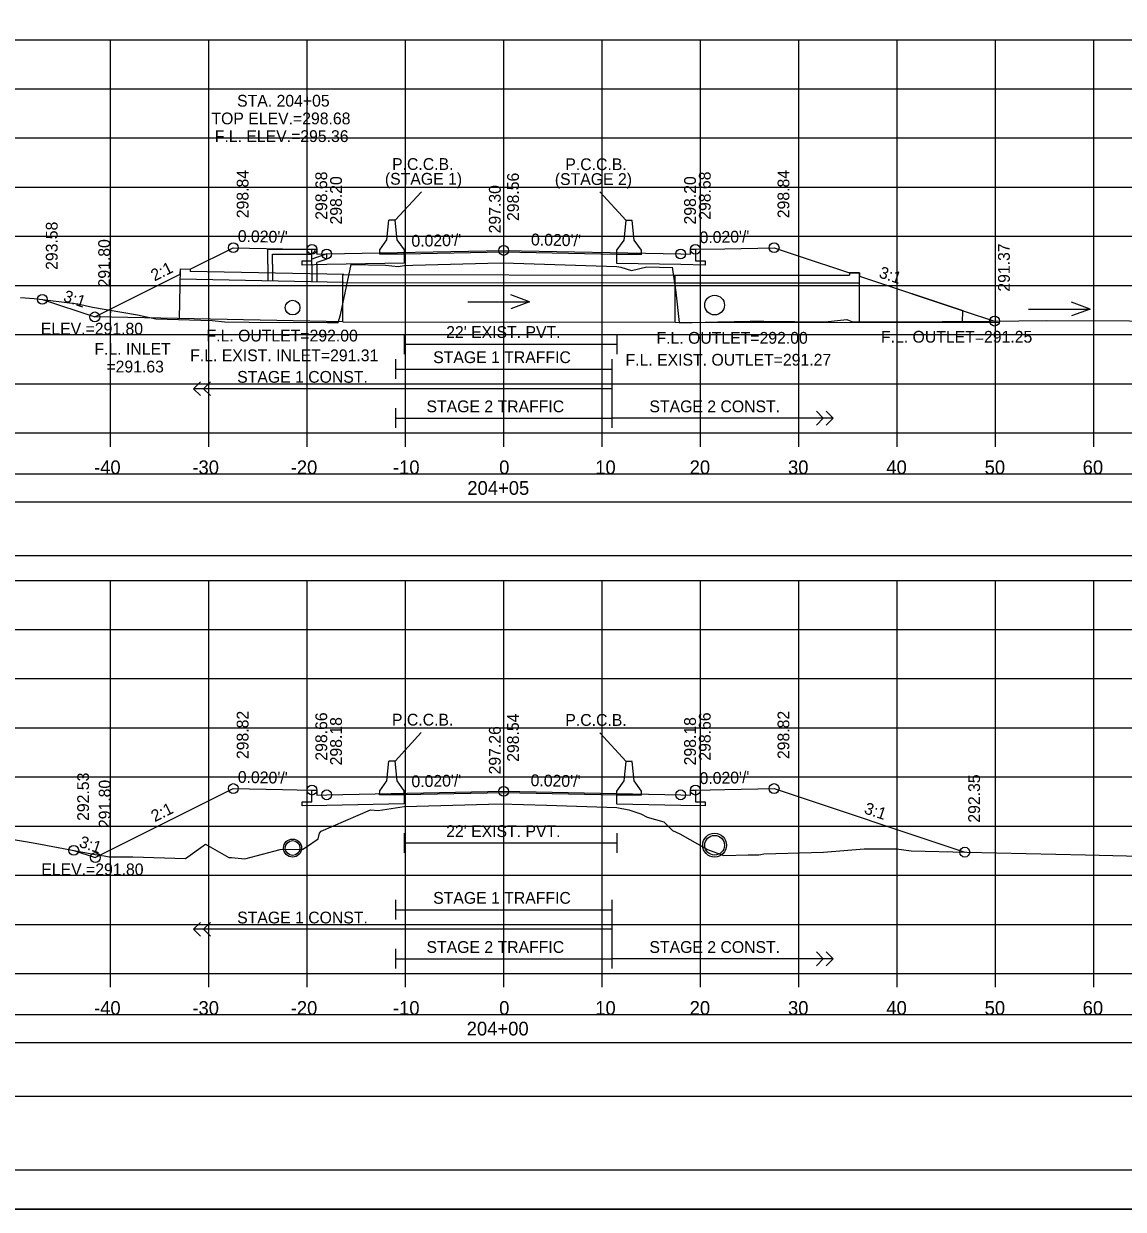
# Model space of a CAD drawing. Extents: x 1368122 to 1710785, y 373130 to 557566.
# Drawn here: x 1369973.4 to 1370085.2, y 373770.3 to 373890.9 of the extents above; entities that cross this region are included whole.
import ezdxf

# ---------------------------------------------------------------- set-up
doc = ezdxf.new("R2010")
doc.units = 0
for name, color, linetype in [('R_Alt Surface', 7, 'Continuous'), ('R_Axis', 7, 'Continuous'), ('R_Axis Annot', 7, 'Continuous'), ('R_Border', 7, 'Continuous'), ('R_Exist Surface', 7, 'Continuous'), ('R_Fin Surface', 7, 'Continuous'), ('R_Grid', 7, 'Continuous'), ('R_MOT', 7, 'Continuous'), ('R_No Plot', 7, 'Continuous'), ('R_Striping', 7, 'Continuous'), ('R_Water', 7, 'Continuous'), ('R_Water Annot', 7, 'Continuous'), ('R_Xsect Elev', 7, 'Continuous'), ('R_Xsect Slope', 7, 'Continuous')]:
    doc.layers.add(name, color=color, linetype=linetype)

msp = doc.modelspace()

# ---------------------------------------------------------------- linework, layer by layer
for points in [[(1369873.09, 373842.32), (1370171.39, 373842.32), (1370171.39, 373845.13), (1369873.09, 373845.13)], [(1369873.09, 373836.85), (1370171.39, 373836.85), (1370171.39, 373842.26), (1369873.09, 373842.26)], [(1369873.09, 373787.32), (1370171.39, 373787.32), (1370171.39, 373790.13), (1369873.09, 373790.13)], [(1369873.09, 373781.85), (1370171.39, 373781.85), (1370171.39, 373787.26), (1369873.09, 373787.26)]]:
    msp.add_lwpolyline(points, close=True)
at = {"layer": 'R_Alt Surface'}
for points in [[(1370041.74, 373868), (1370041.74, 373866.83), (1370042.74, 373866.81), (1370042.74, 373866.39), (1370040.24, 373866.44), (1370033.75, 373866.57), (1370033.75, 373867.48), (1370022.24, 373867.71), (1370012.13, 373867.51), (1370012.13, 373866.59), (1370004.24, 373866.44), (1370001.74, 373866.39), (1370001.74, 373866.81), (1370002.74, 373866.83), (1370002.74, 373868)], [(1370012.13, 373859.34), (1370012.13, 373857.34)], [(1370033.75, 373859.34), (1370033.75, 373857.34)], [(1370012.13, 373858.34), (1370033.75, 373858.34)], [(1370041.74, 373812.98), (1370041.74, 373811.8), (1370042.74, 373811.78), (1370042.74, 373811.37), (1370040.24, 373811.42), (1370033.75, 373811.54), (1370033.75, 373812.46), (1370022.24, 373812.69), (1370012.13, 373812.49), (1370012.12, 373811.57), (1370004.24, 373811.42), (1370001.74, 373811.37), (1370001.74, 373811.78), (1370002.74, 373811.8), (1370002.74, 373812.98)], [(1370012.13, 373808.61), (1370012.13, 373806.61)], [(1370033.75, 373808.61), (1370033.75, 373806.61)], [(1370012.13, 373807.61), (1370033.75, 373807.61)]]:
    msp.add_lwpolyline(points, dxfattribs=at)
at = {"layer": 'R_Axis'}
for p, q in [((1369872.24, 373849.32), (1370172.24, 373849.32)), ((1369982.24, 373847.92), (1369982.24, 373849.32)), ((1369992.24, 373847.92), (1369992.24, 373849.32)), ((1370002.24, 373847.92), (1370002.24, 373849.32)), ((1370012.24, 373847.92), (1370012.24, 373849.32)), ((1370022.24, 373847.92), (1370022.24, 373849.32)), ((1370032.24, 373847.92), (1370032.24, 373849.32)), ((1370042.24, 373847.92), (1370042.24, 373849.32)), ((1370052.24, 373847.92), (1370052.24, 373849.32)), ((1370062.24, 373847.92), (1370062.24, 373849.32)), ((1370072.24, 373847.92), (1370072.24, 373849.32)), ((1370082.24, 373847.92), (1370082.24, 373849.32)), ((1369872.24, 373794.32), (1370172.24, 373794.32)), ((1369982.24, 373792.92), (1369982.24, 373794.32)), ((1369992.24, 373792.92), (1369992.24, 373794.32)), ((1370002.24, 373792.92), (1370002.24, 373794.32)), ((1370012.24, 373792.92), (1370012.24, 373794.32)), ((1370022.24, 373792.92), (1370022.24, 373794.32)), ((1370032.24, 373792.92), (1370032.24, 373794.32)), ((1370042.24, 373792.92), (1370042.24, 373794.32)), ((1370052.24, 373792.92), (1370052.24, 373794.32)), ((1370062.24, 373792.92), (1370062.24, 373794.32)), ((1370072.24, 373792.92), (1370072.24, 373794.32)), ((1370082.24, 373792.92), (1370082.24, 373794.32))]:
    msp.add_line(p, q, dxfattribs=at)
at = {"layer": 'R_Border'}
msp.add_line((1370180.42, 373774.32), (1369864.24, 373774.32), dxfattribs=at)
at = {"layer": 'R_Exist Surface'}
for points in [[(1369973.09, 373863.08), (1369974.48, 373863), (1369978.95, 373862.45), (1369980.42, 373862.12), (1369985.01, 373861.33), (1369986.86, 373860.92), (1369992.59, 373860.76), (1369993.86, 373860.63), (1369996.35, 373860.6), (1370004.32, 373860.55), (1370005.4, 373860.55), (1370005.66, 373861.32), (1370006.72, 373866.46), (1370010.23, 373866.38), (1370011.52, 373866.25), (1370012.13, 373866.34), (1370012.99, 373866.37), (1370021.9, 373866.63), (1370023.23, 373866.59), (1370033.75, 373866.26), (1370034.15, 373866.17), (1370035.24, 373865.83), (1370036.8, 373866.23), (1370039.36, 373866.13), (1370039.39, 373866.18), (1370039.76, 373863.63), (1370040.09, 373860.54), (1370041.41, 373860.54), (1370044.01, 373860.62), (1370047.32, 373860.69), (1370048.34, 373860.67), (1370048.69, 373860.67), (1370054.92, 373860.63), (1370057.15, 373860.87), (1370057.72, 373860.63), (1370058.8, 373860.62), (1370066.82, 373860.65), (1370068.93, 373860.64), (1370077.46, 373860.77), (1370094.3, 373860.69)], [(1369971.62, 373808.1), (1369974.61, 373807.6), (1369981.08, 373806.37), (1369981.61, 373806.3), (1369982.11, 373806.18), (1369984.53, 373806.19), (1369989.87, 373806.04), (1369991.92, 373807.48), (1369994.3, 373806.13), (1369994.55, 373806.13), (1369995.91, 373805.99), (1369999.52, 373806.94), (1370001.83, 373806.96), (1370002.19, 373807.21), (1370003.39, 373808.01), (1370003.5, 373808.61), (1370003.68, 373808.81), (1370008.69, 373810.99), (1370009.46, 373810.91), (1370012.13, 373811.3), (1370015.85, 373811.41), (1370021.93, 373811.59), (1370026.59, 373811.45), (1370033.75, 373811.22), (1370034.98, 373810.96), (1370036.17, 373810.58), (1370036.83, 373810.22), (1370038.53, 373809.77), (1370039.42, 373808.88), (1370040.15, 373808.53), (1370042.98, 373806.95), (1370044.64, 373806.32), (1370047.1, 373806.41), (1370048.19, 373806.39), (1370048.38, 373806.42), (1370048.71, 373806.5), (1370054.75, 373806.68), (1370058.9, 373807), (1370062.17, 373807.01), (1370063.69, 373806.8), (1370069.33, 373806.67), (1370081.39, 373806.39), (1370092.52, 373806.13)]]:
    msp.add_lwpolyline(points, dxfattribs=at)
at = {"layer": 'R_Fin Surface'}
for points in [[(1369975.33, 373862.9), (1369980.66, 373861.12), (1369989.35, 373865.47), (1369989.36, 373866), (1369990.36, 373865.98), (1369994.74, 373868.16), (1369999.74, 373868.06), (1370002.74, 373868), (1370003.24, 373868), (1370003.24, 373867.5), (1370004.24, 373867.52), (1370022.24, 373867.88), (1370040.24, 373867.52), (1370041.24, 373867.5), (1370041.24, 373868), (1370041.74, 373868), (1370044.74, 373868.06), (1370049.74, 373868.16), (1370054.22, 373866.67), (1370055.28, 373866.32), (1370057.42, 373865.61), (1370058.42, 373865.61), (1370058.42, 373865.27), (1370069.07, 373861.72), (1370072.16, 373860.69)], [(1369978.52, 373806.85), (1369980.71, 373806.12), (1369994.74, 373813.14), (1369999.74, 373813.04), (1370002.74, 373812.98), (1370003.24, 373812.98), (1370003.24, 373812.48), (1370004.24, 373812.5), (1370022.24, 373812.86), (1370040.24, 373812.5), (1370041.24, 373812.48), (1370041.24, 373812.98), (1370041.74, 373812.98), (1370044.74, 373813.04), (1370049.74, 373813.14), (1370069.13, 373806.67)]]:
    msp.add_lwpolyline(points, dxfattribs=at)
at = {"layer": 'R_Grid'}
for p, q in [((1369872.24, 373889.32), (1370172.24, 373889.32)), ((1369982.24, 373849.32), (1369982.24, 373889.32)), ((1369992.24, 373849.32), (1369992.24, 373889.32)), ((1370002.24, 373849.32), (1370002.24, 373889.32)), ((1370012.24, 373849.32), (1370012.24, 373889.32)), ((1370022.24, 373849.32), (1370022.24, 373889.32)), ((1370032.24, 373849.32), (1370032.24, 373889.32)), ((1370042.24, 373849.32), (1370042.24, 373889.32)), ((1370052.24, 373849.32), (1370052.24, 373889.32)), ((1370062.24, 373849.32), (1370062.24, 373889.32)), ((1370072.24, 373849.32), (1370072.24, 373889.32)), ((1370082.24, 373849.32), (1370082.24, 373889.32)), ((1369872.24, 373884.32), (1370172.24, 373884.32)), ((1369872.24, 373879.32), (1370172.24, 373879.32)), ((1369872.24, 373874.32), (1370172.24, 373874.32)), ((1369872.24, 373869.32), (1370172.24, 373869.32)), ((1369872.24, 373864.32), (1370172.24, 373864.32)), ((1369872.24, 373859.32), (1370172.24, 373859.32)), ((1369872.24, 373854.32), (1370172.24, 373854.32)), ((1369872.24, 373849.32), (1370172.24, 373849.32)), ((1369872.24, 373834.32), (1370172.24, 373834.32)), ((1369982.24, 373794.32), (1369982.24, 373834.32)), ((1369992.24, 373794.32), (1369992.24, 373834.32)), ((1370002.24, 373794.32), (1370002.24, 373834.32)), ((1370012.24, 373794.32), (1370012.24, 373834.32)), ((1370022.24, 373794.32), (1370022.24, 373834.32)), ((1370032.24, 373794.32), (1370032.24, 373834.32)), ((1370042.24, 373794.32), (1370042.24, 373834.32)), ((1370052.24, 373794.32), (1370052.24, 373834.32)), ((1370062.24, 373794.32), (1370062.24, 373834.32)), ((1370072.24, 373794.32), (1370072.24, 373834.32)), ((1370082.24, 373794.32), (1370082.24, 373834.32)), ((1369872.24, 373829.32), (1370172.24, 373829.32)), ((1369872.24, 373824.32), (1370172.24, 373824.32)), ((1369872.24, 373819.32), (1370172.24, 373819.32)), ((1369872.24, 373814.32), (1370172.24, 373814.32)), ((1369872.24, 373809.32), (1370172.24, 373809.32)), ((1369872.24, 373804.32), (1370172.24, 373804.32)), ((1369872.24, 373799.32), (1370172.24, 373799.32)), ((1369872.24, 373794.32), (1370172.24, 373794.32))]:
    msp.add_line(p, q, dxfattribs=at)
at = {"layer": 'R_MOT'}
for p, q in [((1370010.36, 373868.97), (1370010.57, 373870.95)), ((1370010.88, 373870.95), (1370010.57, 373870.95)), ((1370011.19, 373870.95), (1370010.88, 373870.95)), ((1370011.4, 373868.97), (1370011.19, 373870.95)), ((1370034.48, 373868.94), (1370034.69, 373870.92)), ((1370035, 373870.92), (1370034.69, 373870.92)), ((1370035.31, 373870.92), (1370035, 373870.92)), ((1370035.52, 373868.94), (1370035.31, 373870.92)), ((1370009.64, 373867.93), (1370010.36, 373868.97)), ((1370012.14, 373867.93), (1370011.4, 373868.97)), ((1370033.76, 373867.9), (1370034.48, 373868.94)), ((1370036.26, 373867.9), (1370035.52, 373868.94)), ((1370009.63, 373867.51), (1370009.64, 373867.93)), ((1370012.13, 373867.51), (1370009.63, 373867.51)), ((1370012.13, 373867.51), (1370012.14, 373867.93)), ((1370033.75, 373867.48), (1370033.76, 373867.9)), ((1370036.25, 373867.48), (1370033.75, 373867.48)), ((1370036.25, 373867.48), (1370036.26, 373867.9)), ((1370010.35, 373813.94), (1370010.56, 373815.92)), ((1370010.87, 373815.92), (1370010.56, 373815.92)), ((1370011.19, 373815.92), (1370010.87, 373815.92)), ((1370011.4, 373813.94), (1370011.19, 373815.92)), ((1370034.48, 373813.92), (1370034.69, 373815.9)), ((1370035, 373815.9), (1370034.69, 373815.9)), ((1370035.31, 373815.9), (1370035, 373815.9)), ((1370035.52, 373813.92), (1370035.31, 373815.9)), ((1370009.63, 373812.9), (1370010.35, 373813.94)), ((1370012.13, 373812.9), (1370011.4, 373813.94)), ((1370033.76, 373812.87), (1370034.48, 373813.92)), ((1370036.26, 373812.87), (1370035.52, 373813.92)), ((1370009.62, 373812.49), (1370009.63, 373812.9)), ((1370012.13, 373812.49), (1370009.62, 373812.49)), ((1370012.13, 373812.49), (1370012.13, 373812.9)), ((1370033.75, 373812.46), (1370033.76, 373812.87)), ((1370036.25, 373812.46), (1370033.75, 373812.46)), ((1370036.25, 373812.46), (1370036.26, 373812.87))]:
    msp.add_line(p, q, dxfattribs=at)
at = {"layer": 'R_No Plot'}
msp.add_line((1369851.84, 373770.34), (1370185.17, 373770.34), dxfattribs=at)
for points in [[(1369851.83, 373983.68), (1370185.17, 373983.68), (1370185.17, 373770.34), (1369851.83, 373770.34)], [(1370098.16, 373979.78), (1370117.78, 373979.78), (1370117.78, 373969.9), (1370133.89, 373969.9), (1370157.09, 373969.9), (1370157.21, 373941.75), (1370180.42, 373941.75), (1370180.42, 373774.32), (1369864.24, 373774.32), (1369864.24, 373979.78)]]:
    msp.add_lwpolyline(points, close=True, dxfattribs=at)
for centre, radius in [((1369994.74, 373868.16), 0.5), ((1370002.74, 373868), 0.5), ((1370041.74, 373868), 0.5), ((1370049.74, 373868.16), 0.5), ((1370004.24, 373867.52), 0.5), ((1370022.24, 373867.88), 0.5), ((1370040.24, 373867.52), 0.5), ((1369975.33, 373862.9), 0.5), ((1369980.66, 373861.12), 0.5), ((1370072.16, 373860.69), 0.5), ((1369994.74, 373813.14), 0.5), ((1370002.74, 373812.98), 0.5), ((1370004.24, 373812.5), 0.5), ((1370022.24, 373812.86), 0.5), ((1370040.24, 373812.5), 0.5), ((1370041.74, 373812.98), 0.5), ((1370049.74, 373813.14), 0.5), ((1370043.69, 373807.38), 1.21), ((1369978.52, 373806.85), 0.5), ((1370000.77, 373807.09), 0.917), ((1370069.13, 373806.67), 0.5), ((1369980.71, 373806.12), 0.5)]:
    msp.add_circle(centre, radius, dxfattribs=at)
at = {"layer": 'R_Striping'}
for p, q in [((1370011.19, 373870.95), (1370013.87, 373873.86)), ((1370034.69, 373870.92), (1370032.01, 373873.83)), ((1369990.71, 373853.82), (1369991.41, 373854.53)), ((1369991.71, 373853.82), (1369992.41, 373854.53)), ((1369991.41, 373853.12), (1369990.71, 373853.82)), ((1369992.41, 373853.12), (1369991.71, 373853.82)), ((1370054.74, 373850.82), (1370054.04, 373851.53)), ((1370055.74, 373850.82), (1370055.04, 373851.53)), ((1370055.74, 373850.82), (1370033.24, 373850.82)), ((1370054.04, 373850.12), (1370054.74, 373850.82)), ((1370055.04, 373850.12), (1370055.74, 373850.82)), ((1370011.19, 373815.92), (1370013.86, 373818.83)), ((1370034.69, 373815.9), (1370032.01, 373818.81)), ((1369990.71, 373798.82), (1369991.41, 373799.53)), ((1369991.41, 373798.12), (1369990.71, 373798.82)), ((1369991.71, 373798.82), (1369992.41, 373799.53)), ((1369992.41, 373798.12), (1369991.71, 373798.82)), ((1370054.74, 373795.82), (1370054.04, 373796.53)), ((1370055.74, 373795.82), (1370055.04, 373796.53)), ((1370055.74, 373795.82), (1370033.24, 373795.82)), ((1370054.04, 373795.12), (1370054.74, 373795.82)), ((1370055.04, 373795.12), (1370055.74, 373795.82))]:
    msp.add_line(p, q, dxfattribs=at)
for points in [[(1370011.24, 373856.82), (1370011.24, 373854.82)], [(1370033.24, 373856.82), (1370033.24, 373849.82)], [(1370033.24, 373856.82), (1370033.24, 373854.82)], [(1370011.24, 373855.82), (1370033.24, 373855.82)], [(1370033.24, 373853.82), (1369990.71, 373853.82)], [(1370011.24, 373851.82), (1370011.24, 373849.82)], [(1370011.24, 373850.82), (1370033.24, 373850.82)], [(1370011.24, 373801.82), (1370011.24, 373799.82)], [(1370033.24, 373801.82), (1370033.24, 373794.82)], [(1370033.24, 373801.82), (1370033.24, 373799.82)], [(1370011.24, 373800.82), (1370033.24, 373800.82)], [(1370033.24, 373798.82), (1369990.71, 373798.82)], [(1370011.24, 373796.82), (1370011.24, 373794.82)], [(1370011.24, 373795.82), (1370033.24, 373795.82)]]:
    msp.add_lwpolyline(points, dxfattribs=at)
at = {"layer": 'R_Water'}
for p, q in [((1369998.24, 373868), (1370002.99, 373868)), ((1369998.24, 373866.5), (1369998.24, 373868)), ((1369998.74, 373866.5), (1369998.74, 373867.5)), ((1369998.74, 373867.5), (1370002.74, 373867.5)), ((1370003.07, 373867.84), (1370002.74, 373867.5)), ((1370004.24, 373867.52), (1370002.74, 373867)), ((1370003.07, 373867.84), (1370002.99, 373868)), ((1369989.27, 373860.96), (1369989.36, 373866)), ((1369989.36, 373866), (1369990.36, 373865.98)), ((1369998.24, 373866.5), (1369998.24, 373864.78)), ((1369998.74, 373866.5), (1369998.74, 373864.77)), ((1370002.74, 373866.5), (1370002.74, 373867)), ((1370002.74, 373866.5), (1370002.74, 373864.7)), ((1370004.24, 373866.99), (1370003.24, 373866.65)), ((1370003.24, 373866.5), (1370003.24, 373866.65)), ((1370003.24, 373866.5), (1370003.24, 373864.69)), ((1369982.28, 373861.94), (1369989.35, 373865.47)), ((1370005.96, 373864.63), (1369989.34, 373864.96)), ((1369990.36, 373865.98), (1369990.36, 373865.73)), ((1370005.97, 373865.42), (1369990.36, 373865.73)), ((1370005.88, 373865.42), (1370039.69, 373865.38)), ((1370005.88, 373860.63), (1370005.88, 373865.42)), ((1370039.69, 373860.59), (1370039.69, 373865.38)), ((1370039.69, 373865.38), (1370057.42, 373865.36)), ((1370057.42, 373865.61), (1370057.42, 373865.36)), ((1370058.42, 373865.61), (1370057.42, 373865.61)), ((1370058.41, 373860.57), (1370058.42, 373865.61)), ((1370058.42, 373865.28), (1370068.92, 373861.78)), ((1370005.88, 373864.63), (1370039.69, 373864.59)), ((1370039.69, 373864.59), (1370058.42, 373864.57)), ((1369982.27, 373861.09), (1369982.28, 373861.94)), ((1370068.91, 373860.56), (1370068.92, 373861.78)), ((1370005.88, 373860.63), (1369980.66, 373861.12)), ((1370005.88, 373860.63), (1370039.69, 373860.59)), ((1370039.69, 373860.59), (1370072.59, 373860.56))]:
    msp.add_line(p, q, dxfattribs=at)
msp.add_lwpolyline([(1370004.24, 373866.99), (1370004.24, 373867.52)], dxfattribs=at)
for centre, radius in [((1370000.77, 373862.07), 0.75), ((1370043.69, 373862.32), 1), ((1370043.69, 373807.38), 1), ((1370000.77, 373807.09), 0.75)]:
    msp.add_circle(centre, radius, dxfattribs=at)
at = {"layer": 'R_Water Annot'}
for p, q in [((1370018.59, 373862.65), (1370024.87, 373862.65)), ((1370024.87, 373862.65), (1370022.95, 373863.35)), ((1370024.87, 373862.65), (1370022.95, 373861.95)), ((1370081.89, 373861.92), (1370079.97, 373862.62)), ((1370075.61, 373861.92), (1370081.89, 373861.92)), ((1370081.89, 373861.92), (1370079.97, 373861.22))]:
    msp.add_line(p, q, dxfattribs=at)
at = {"layer": 'R_Xsect Elev'}
for p, q in [((1370022.24, 373866.62), (1370022.24, 373876.62)), ((1370022.24, 373811.58), (1370022.24, 373821.58))]:
    msp.add_line(p, q, dxfattribs=at)

# ---------------------------------------------------------------- texts
at = {"layer": 'R_Axis Annot'}
for s, p in [('-40', (1369980.58, 373845.12)), ('-30', (1369990.58, 373845.12)), ('-20', (1370000.58, 373845.12)), ('-10', (1370010.98, 373845.12)), ('0', (1370021.78, 373845.12)), ('10', (1370031.55, 373845.12)), ('20', (1370041.15, 373845.12)), ('30', (1370051.15, 373845.12)), ('40', (1370061.15, 373845.12)), ('50', (1370071.15, 373845.12)), ('60', (1370081.12, 373845.12)), ('204+05', (1370018.54, 373843.02)), ('-40', (1369980.58, 373790.12)), ('-30', (1369990.58, 373790.12)), ('-20', (1370000.58, 373790.12)), ('-10', (1370010.98, 373790.12)), ('0', (1370021.78, 373790.12)), ('10', (1370031.55, 373790.12)), ('20', (1370041.15, 373790.12)), ('30', (1370051.15, 373790.12)), ('40', (1370061.15, 373790.12)), ('50', (1370071.15, 373790.12)), ('60', (1370081.12, 373790.12)), ('204+00', (1370018.48, 373788.02))]:
    msp.add_text(s, height=1.4, dxfattribs=at).set_placement(p)
at = {"layer": 'R_Striping'}
for s, p in [('P.C.C.B. ', (1370010.89, 373876.07)), ('P.C.C.B.', (1370028.51, 373876.05)), ('(STAGE 1)', (1370010.16, 373874.57)), ('(STAGE 2)', (1370027.44, 373874.54)), ('STAGE 1 TRAFFIC', (1370015.07, 373856.42)), ('STAGE 1 CONST.', (1369995.14, 373854.42)), ('STAGE 2 TRAFFIC', (1370014.39, 373851.42)), ('STAGE 2 CONST.', (1370037.06, 373851.42)), ('P.C.C.B.', (1370010.88, 373819.55)), ('P.C.C.B.', (1370028.51, 373819.52)), ('STAGE 1 TRAFFIC', (1370015.07, 373801.42)), ('STAGE 1 CONST.', (1369995.14, 373799.42)), ('STAGE 2 TRAFFIC', (1370014.39, 373796.42)), ('STAGE 2 CONST.', (1370037.06, 373796.42))]:
    msp.add_text(s, height=1.2, dxfattribs=at).set_placement(p)
at = {"layer": 'R_Water'}
for p in [(1370016.39, 373858.98), (1370016.39, 373808.21)]:
    msp.add_text("22' EXIST. PVT.", height=1.2, dxfattribs=at).set_placement(p)
at = {"layer": 'R_Water Annot'}
for s, p in [('STA. 204+05', (1369995.13, 373882.51)), ('TOP ELEV.=298.68', (1369992.52, 373880.71)), ('F.L. ELEV.=295.36', (1369992.86, 373878.91)), ('F.L. OUTLET=292.00', (1369992.02, 373858.62)), ('F.L. OUTLET=292.00', (1370037.78, 373858.39)), ('F.L. OUTLET=291.25', (1370060.61, 373858.5)), ('F.L. INLET', (1369980.62, 373857.27)), ('F.L. EXIST. INLET=291.31', (1369990.36, 373856.61)), ('=291.63', (1369981.84, 373855.47)), ('F.L. EXIST. OUTLET=291.27', (1370034.63, 373856.16))]:
    msp.add_text(s, height=1.2, dxfattribs=at).set_placement(p)
at = {"layer": 'R_Xsect Elev'}
for s, p in [('298.84', (1369996.29, 373871.16)), ('298.68', (1370004.29, 373871)), ('298.56', (1370023.79, 373870.88)), ('298.68', (1370043.29, 373871)), ('298.84', (1370051.29, 373871.16)), ('298.20', (1370005.79, 373870.52)), ('297.30', (1370021.94, 373869.62)), ('298.20', (1370041.79, 373870.52)), ('293.58', (1369976.88, 373865.9)), ('291.80', (1369982.21, 373864.12)), ('291.37', (1370073.71, 373863.69)), ('298.82', (1369996.29, 373816.14)), ('298.66', (1370004.29, 373815.98)), ('298.18', (1370005.79, 373815.5)), ('298.54', (1370023.79, 373815.86)), ('298.18', (1370041.79, 373815.5)), ('298.66', (1370043.29, 373815.98)), ('298.82', (1370051.29, 373816.14)), ('297.26', (1370021.94, 373814.58)), ('292.53', (1369980.07, 373809.85)), ('292.35', (1370070.68, 373809.67)), ('291.80', (1369982.26, 373809.12))]:
    msp.add_text(s, height=1.2, rotation=90, dxfattribs=at).set_placement(p)
for p in [(1369975.17, 373859.32), (1369975.22, 373804.32)]:
    msp.add_text('ELEV.=291.80', height=1.2, dxfattribs=at).set_placement(p)
at = {"layer": 'R_Xsect Slope'}
for s, rotation, p in [("0.020'/'", 358.8542, (1369995.19, 373868.75)), ("0.020'/'", 1.1458, (1370012.87, 373868.25)), ("0.020'/'", 358.8542, (1370025.01, 373868.4)), ("0.020'/'", 1.1458, (1370042.17, 373868.61)), ('2:1', 26.5651, (1369986.73, 373864.72)), ('3:1', 341.5651, (1370060.32, 373865.16)), ('3:1', 341.5651, (1369977.37, 373862.75)), ("0.020'/'", 358.8542, (1369995.19, 373813.73)), ("0.020'/'", 1.1458, (1370012.87, 373813.27)), ("0.020'/'", 358.8542, (1370024.97, 373813.39)), ("0.020'/'", 1.1458, (1370042.17, 373813.59)), ('3:1', 341.5651, (1370058.81, 373810.64)), ('2:1', 26.5651, (1369986.76, 373809.71)), ('3:1', 341.5651, (1369978.98, 373807.23))]:
    msp.add_text(s, height=1.2, rotation=rotation, dxfattribs=at).set_placement(p)

doc.saveas('drawing.dxf')
